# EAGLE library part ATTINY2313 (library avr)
MICROCONTROLLER 2 Kbytes FLASH 128 bytes SRAM 128 bytes EEPROM USART USI
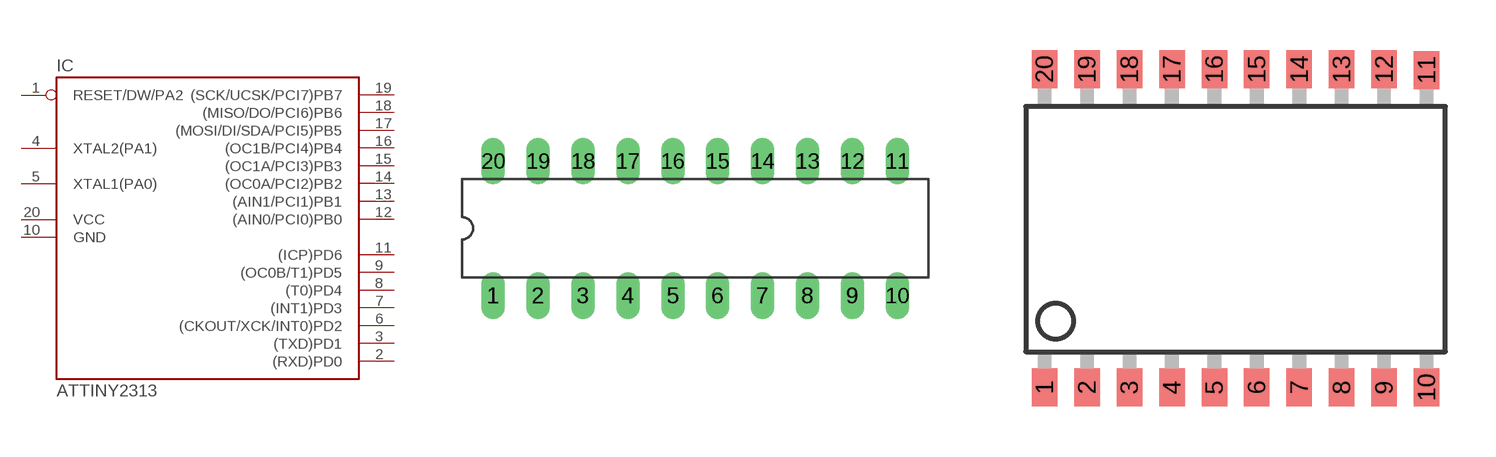
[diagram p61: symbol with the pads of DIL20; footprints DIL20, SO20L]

Designator prefix IC

## ATTINY2313-20P, ATTINY2313V-10P  [DIL20]
1  RESET/DW/PA2
2  (RXD)PD0
3  (TXD)PD1
4  XTAL2(PA1)
5  XTAL1(PA0)
6  (CKOUT/XCK/INT0)PD2
7  (INT1)PD3
8  (T0)PD4
9  (OC0B/T1)PD5
10  GND  pwr
11  (ICP)PD6
12  (AIN0/PCI0)PB0
13  (AIN1/PCI1)PB1
14  (OC0A/PCI2)PB2
15  (OC1A/PCI3)PB3
16  (OC1B/PCI4)PB4
17  (MOSI/DI/SDA/PCI5)PB5
18  (MISO/DO/PCI6)PB6
19  (SCK/UCSK/PCI7)PB7
20  VCC  pwr

## ATTINY2313-20S, ATTINY2313V-10S  [SO20L]
Pads as for DIL20

## ATTINY2313-20M, ATTINY2313V-10M  [MLF20]
1  (TXD)PD1
2  XTAL2(PA1)
3  XTAL1(PA0)
4  (CKOUT/XCK/INT0)PD2
5  (INT1)PD3
6  (T0)PD4
7  (OC0B/T1)PD5
8  GND  pwr
9  (ICP)PD6
10  (AIN0/PCI0)PB0
11  (AIN1/PCI1)PB1
12  (OC0A/PCI2)PB2
13  (OC1A/PCI3)PB3
14  (OC1B/PCI4)PB4
15  (MOSI/DI/SDA/PCI5)PB5
16  (MISO/DO/PCI6)PB6
17  (SCK/UCSK/PCI7)PB7
18  VCC  pwr
19  RESET/DW/PA2
20  (RXD)PD0

## Footprint DIL20 (pad centres in mm)
Dual In Line
drill 0.813 long: 1 -11.43,-3.81; 2 -8.89,-3.81; 3 -6.35,-3.81; 4 -3.81,-3.81; 5 -1.27,-3.81; 6 1.27,-3.81; 7 3.81,-3.81; 8 6.35,-3.81; 9 8.89,-3.81; 10 11.43,-3.81; 11 11.43,3.81; 12 8.89,3.81; 13 6.35,3.81; 14 3.81,3.81; 15 1.27,3.81; 16 -1.27,3.81; 17 -3.81,3.81; 18 -6.35,3.81; 19 -8.89,3.81; 20 -11.43,3.81

## Footprint SO20L (pad centres in mm)
Small Outline Package
smd 0.762 x 1.143: 1 -5.08,-5.131; 2 -3.81,-5.131; 3 -2.54,-5.131; 4 -1.27,-5.131; 5 0,-5.131; 6 1.27,-5.131; 7 2.54,-5.131; 8 3.81,-5.131; 9 5.08,-5.131; 10 6.35,-5.131; 11 6.35,4.369; 12 5.08,4.394; 13 3.81,4.394; 14 2.54,4.394; 15 1.27,4.394; 16 0,4.394; 17 -1.27,4.394; 18 -2.54,4.394; 19 -3.81,4.394; 20 -5.08,4.394

## Footprint MLF20 (pad centres in mm)
HP-VFQFP-N20 Micro Lead Frame package (MLF)
smd 0.9 x 0.35: 1 -2.25,1.3; 2 -2.25,0.65; 3 -2.25,0; 4 -2.25,-0.65; 5 -2.25,-1.3; 11 2.25,-1.3; 12 2.25,-0.65; 13 2.25,0; 14 2.25,0.65; 15 2.25,1.3
smd 0.35 x 0.9: 6 -1.3,-2.25; 7 -0.65,-2.25; 8 0,-2.25; 9 0.65,-2.25; 10 1.3,-2.25; 16 1.3,2.25; 17 0.65,2.25; 18 0,2.25; 19 -0.65,2.25; 20 -1.3,2.25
